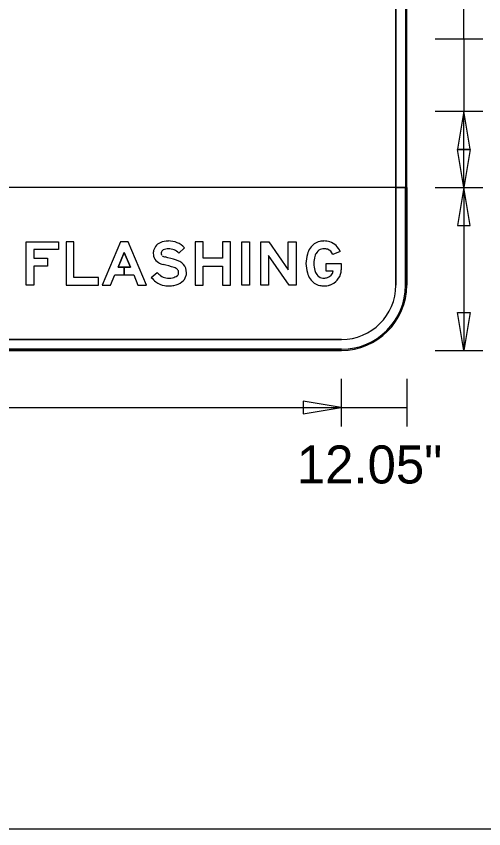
# Model space of a CAD drawing. Extents: x 17890628 to 17890817, y 17897493 to 17897992.
# Drawn here: x 17890789.24 to 17890796.4, y 17897520.54 to 17897533 of the extents above; entities that cross this region are included whole.
import ezdxf

# ---------------------------------------------------------------- set-up
doc = ezdxf.new("R2010")
doc.units = 0
for name, color, linetype in [('GSBWFill', 7, 'Continuous'), ('GSColorFill', 7, 'Continuous'), ('GSDims', 7, 'Continuous'), ('GSOutline', 7, 'Continuous'), ('SheetLinesMisc2_dp', 7, 'Continuous')]:
    doc.layers.add(name, color=color, linetype=linetype)

msp = doc.modelspace()

# ---------------------------------------------------------------- linework, layer by layer
at = {"layer": 'GSBWFill'}
for p, q in [((17890795.055, 17897536.876), (17890795.055, 17897528.876)), ((17890795.222, 17897528.876), (17890795.222, 17897536.876)), ((17890795.222, 17897530.376), (17890775.222, 17897530.376)), ((17890795.055, 17897530.21), (17890795.055, 17897530.376)), ((17890795.055, 17897530.376), (17890795.222, 17897530.376)), ((17890795.222, 17897530.376), (17890795.222, 17897528.876)), ((17890795.222, 17897528.876), (17890795.222, 17897530.376)), ((17890795.055, 17897528.876), (17890795.055, 17897530.21)), ((17890776.222, 17897528.043), (17890794.222, 17897528.043)), ((17890794.222, 17897528.043), (17890776.224, 17897528.043)), ((17890794.222, 17897527.876), (17890776.222, 17897527.876)), ((17890776.222, 17897527.876), (17890794.222, 17897527.876)), ((17890776.224, 17897527.876), (17890794.222, 17897527.876))]:
    msp.add_line(p, q, dxfattribs=at)
for points in [[(17890789.505, 17897529.17), (17890789.505, 17897528.876), (17890789.385, 17897528.876), (17890789.385, 17897529.543), (17890789.885, 17897529.543), (17890789.885, 17897529.423), (17890789.505, 17897529.423), (17890789.505, 17897529.29), (17890789.715, 17897529.29), (17890789.715, 17897529.17)], [(17890790.499, 17897528.876), (17890790.499, 17897528.993), (17890790.119, 17897528.993), (17890790.119, 17897529.543), (17890789.999, 17897529.543), (17890789.999, 17897528.876)], [(17890790.986, 17897529.153), (17890790.892, 17897529.153), (17890790.892, 17897529.033), (17890791.036, 17897529.033), (17890791.102, 17897528.876), (17890791.232, 17897528.876), (17890790.952, 17897529.543), (17890790.832, 17897529.543), (17890790.552, 17897528.876), (17890790.682, 17897528.876), (17890790.748, 17897529.033), (17890790.892, 17897529.033), (17890790.892, 17897529.153), (17890790.798, 17897529.153), (17890790.892, 17897529.376)], [(17890792.399, 17897529.29), (17890792.099, 17897529.29), (17890792.099, 17897529.543), (17890791.979, 17897529.543), (17890791.979, 17897528.876), (17890792.099, 17897528.876), (17890792.099, 17897529.17), (17890792.399, 17897529.17), (17890792.399, 17897528.876), (17890792.519, 17897528.876), (17890792.519, 17897529.543), (17890792.399, 17897529.543)], [(17890792.692, 17897528.876), (17890792.692, 17897529.543), (17890792.812, 17897529.543), (17890792.812, 17897528.876)], [(17890793.525, 17897529.543), (17890793.525, 17897528.876), (17890793.422, 17897528.876), (17890793.105, 17897529.333), (17890793.105, 17897528.876), (17890792.985, 17897528.876), (17890792.985, 17897529.543), (17890793.106, 17897529.543), (17890793.405, 17897529.111), (17890793.405, 17897529.543)]]:
    msp.add_lwpolyline(points, close=True, dxfattribs=at)
for points in [[(17890791.815, 17897529.451), (17890791.729, 17897529.367)], [(17890794.201, 17897529.392), (17890794.089, 17897529.347)], [(17890794.095, 17897529.09), (17890793.985, 17897529.09), (17890793.985, 17897529.21), (17890794.219, 17897529.21), (17890794.219, 17897529.114)], [(17890791.305, 17897528.994), (17890791.396, 17897529.073)]]:
    msp.add_lwpolyline(points, dxfattribs=at)
for centre, radius, start, end in [((17890791.511, 17897529.368), 0.174, 113.3248, 174.1421), ((17890791.568, 17897529.236), 0.318, 90, 113.3248), ((17890791.568, 17897529.21), 0.345, 44.4342, 90), ((17890793.943, 17897529.313), 0.24, 103.1315, 146.7742), ((17890793.954, 17897529.265), 0.289, 90, 103.1315), ((17890793.954, 17897529.275), 0.28, 71.2015, 90), ((17890793.961, 17897529.295), 0.259, 22.0367, 71.2015), ((17890791.511, 17897529.368), 0.0543, 113.3248, 174.1421), ((17890791.568, 17897529.236), 0.198, 90, 113.3248), ((17890791.568, 17897529.21), 0.225, 44.4342, 90), ((17890794.033, 17897529.254), 0.348, 146.7742, 163.4624), ((17890793.943, 17897529.313), 0.12, 103.1315, 146.7742), ((17890793.954, 17897529.265), 0.169, 90, 103.1315), ((17890793.954, 17897529.275), 0.16, 71.2015, 90), ((17890793.961, 17897529.295), 0.139, 22.0367, 71.2015), ((17890791.527, 17897529.367), 0.191, 174.1421, 201.2247), ((17890791.489, 17897529.352), 0.149, 201.2247, 240.1812), ((17890791.527, 17897529.367), 0.0706, 174.1421, 201.2247), ((17890791.489, 17897529.352), 0.029, 201.2247, 240.1812), ((17890791.558, 17897529.472), 0.168, 240.1812, 256.1067), ((17890790.74, 17897526.168), 3.236, 72.8961, 76.1067), ((17890794.183, 17897529.21), 0.505, 163.4624, 180), ((17890794.183, 17897529.21), 0.385, 163.4624, 180), ((17890794.033, 17897529.254), 0.228, 146.7742, 163.4624), ((17890791.558, 17897529.472), 0.288, 240.1812, 256.1067), ((17890790.74, 17897526.168), 3.116, 72.8961, 76.1067), ((17890791.598, 17897528.955), 0.32, 63.0108, 72.8961), ((17890791.662, 17897529.082), 0.178, 39.5561, 63.0108), ((17890791.646, 17897529.068), 0.199, 0, 39.5561), ((17890794.183, 17897529.21), 0.505, 180, 196.5376), ((17890794.183, 17897529.21), 0.385, 180, 196.5376), ((17890791.657, 17897529.298), 0.344, 220.8202, 232.6492), ((17890791.598, 17897528.955), 0.2, 63.0108, 72.8961), ((17890791.662, 17897529.082), 0.0579, 39.5561, 63.0108), ((17890791.679, 17897529.06), 0.045, 306.0677, 343.4972), ((17890791.646, 17897529.068), 0.0794, 0, 39.5561), ((17890791.651, 17897529.068), 0.0746, 343.4972, 0), ((17890791.651, 17897529.068), 0.195, 343.4972, 0), ((17890794.033, 17897529.165), 0.348, 196.5376, 213.2258), ((17890794.033, 17897529.165), 0.228, 196.5376, 213.2258), ((17890793.943, 17897529.106), 0.12, 213.2258, 256.8685), ((17890793.961, 17897529.124), 0.139, 288.7985, 345.418), ((17890793.961, 17897529.124), 0.259, 288.7985, 349.6765), ((17890794.021, 17897529.114), 0.198, 349.6765, 0), ((17890791.657, 17897529.298), 0.464, 220.8202, 232.6492), ((17890791.56, 17897529.171), 0.305, 232.6492, 260.7349), ((17890791.56, 17897529.171), 0.185, 232.6492, 260.7349), ((17890791.58, 17897529.295), 0.31, 260.7349, 270), ((17890791.58, 17897529.23), 0.245, 270, 281.6446), ((17890791.59, 17897529.182), 0.196, 281.6446, 306.0677), ((17890791.59, 17897529.182), 0.316, 281.6446, 306.0677), ((17890791.679, 17897529.06), 0.165, 306.0677, 343.4972), ((17890793.943, 17897529.106), 0.24, 213.2258, 256.8685), ((17890793.954, 17897529.154), 0.169, 256.8685, 270), ((17890793.954, 17897529.145), 0.16, 270, 288.7985), ((17890791.58, 17897529.295), 0.43, 260.7349, 270), ((17890791.58, 17897529.23), 0.365, 270, 281.6446), ((17890793.954, 17897529.154), 0.289, 256.8685, 270), ((17890793.954, 17897529.145), 0.28, 270, 288.7985), ((17890794.222, 17897528.876), 1, 270, 0), ((17890794.222, 17897528.876), 0.833, 270, 0), ((17890794.222, 17897528.876), 1, 270, 0), ((17890794.222, 17897528.876), 0.833, 270, 0), ((17890794.222, 17897528.876), 1, 270, 0)]:
    msp.add_arc(centre, radius, start, end, dxfattribs=at)
at = {"layer": 'GSColorFill'}
for p, q in [((17890795.055, 17897536.876), (17890795.055, 17897528.876)), ((17890795.205, 17897536.876), (17890795.205, 17897528.876)), ((17890795.222, 17897528.876), (17890795.222, 17897536.876)), ((17890795.222, 17897528.876), (17890795.222, 17897536.876)), ((17890795.222, 17897528.876), (17890795.222, 17897536.876)), ((17890795.222, 17897530.376), (17890775.222, 17897530.376)), ((17890795.055, 17897530.21), (17890795.055, 17897530.376)), ((17890795.055, 17897530.376), (17890795.222, 17897530.376)), ((17890795.205, 17897530.36), (17890795.205, 17897530.376)), ((17890795.205, 17897530.376), (17890795.222, 17897530.376)), ((17890795.205, 17897528.876), (17890795.205, 17897530.36)), ((17890795.222, 17897528.876), (17890795.222, 17897530.376)), ((17890795.222, 17897530.376), (17890795.222, 17897528.876)), ((17890795.222, 17897530.376), (17890795.222, 17897528.876)), ((17890795.055, 17897528.876), (17890795.055, 17897530.21)), ((17890776.222, 17897528.043), (17890794.222, 17897528.043)), ((17890794.222, 17897528.043), (17890776.224, 17897528.043)), ((17890794.222, 17897527.893), (17890776.222, 17897527.893)), ((17890776.222, 17897527.893), (17890794.222, 17897527.893)), ((17890776.222, 17897527.876), (17890794.222, 17897527.876)), ((17890776.222, 17897527.876), (17890794.222, 17897527.876)), ((17890776.222, 17897527.876), (17890794.222, 17897527.876)), ((17890794.222, 17897527.876), (17890776.222, 17897527.876)), ((17890794.222, 17897527.876), (17890776.222, 17897527.876)), ((17890776.224, 17897527.876), (17890794.222, 17897527.876))]:
    msp.add_line(p, q, dxfattribs=at)
for points in [[(17890789.505, 17897529.17), (17890789.505, 17897528.876), (17890789.385, 17897528.876), (17890789.385, 17897529.543), (17890789.885, 17897529.543), (17890789.885, 17897529.423), (17890789.505, 17897529.423), (17890789.505, 17897529.29), (17890789.715, 17897529.29), (17890789.715, 17897529.17)], [(17890790.499, 17897528.876), (17890790.499, 17897528.993), (17890790.119, 17897528.993), (17890790.119, 17897529.543), (17890789.999, 17897529.543), (17890789.999, 17897528.876)], [(17890790.986, 17897529.153), (17890790.892, 17897529.153), (17890790.892, 17897529.033), (17890791.036, 17897529.033), (17890791.102, 17897528.876), (17890791.232, 17897528.876), (17890790.952, 17897529.543), (17890790.832, 17897529.543), (17890790.552, 17897528.876), (17890790.682, 17897528.876), (17890790.748, 17897529.033), (17890790.892, 17897529.033), (17890790.892, 17897529.153), (17890790.798, 17897529.153), (17890790.892, 17897529.376)], [(17890792.399, 17897529.29), (17890792.099, 17897529.29), (17890792.099, 17897529.543), (17890791.979, 17897529.543), (17890791.979, 17897528.876), (17890792.099, 17897528.876), (17890792.099, 17897529.17), (17890792.399, 17897529.17), (17890792.399, 17897528.876), (17890792.519, 17897528.876), (17890792.519, 17897529.543), (17890792.399, 17897529.543)], [(17890792.692, 17897528.876), (17890792.692, 17897529.543), (17890792.812, 17897529.543), (17890792.812, 17897528.876)], [(17890793.525, 17897529.543), (17890793.525, 17897528.876), (17890793.422, 17897528.876), (17890793.105, 17897529.333), (17890793.105, 17897528.876), (17890792.985, 17897528.876), (17890792.985, 17897529.543), (17890793.106, 17897529.543), (17890793.405, 17897529.111), (17890793.405, 17897529.543)]]:
    msp.add_lwpolyline(points, close=True, dxfattribs=at)
for points in [[(17890791.815, 17897529.451), (17890791.729, 17897529.367)], [(17890794.201, 17897529.392), (17890794.089, 17897529.347)], [(17890794.095, 17897529.09), (17890793.985, 17897529.09), (17890793.985, 17897529.21), (17890794.219, 17897529.21), (17890794.219, 17897529.114)], [(17890791.305, 17897528.994), (17890791.396, 17897529.073)]]:
    msp.add_lwpolyline(points, dxfattribs=at)
for centre, radius, start, end in [((17890791.511, 17897529.368), 0.174, 113.3248, 174.1421), ((17890791.568, 17897529.236), 0.318, 90, 113.3248), ((17890791.568, 17897529.21), 0.345, 44.4342, 90), ((17890793.943, 17897529.313), 0.24, 103.1315, 146.7742), ((17890793.954, 17897529.265), 0.289, 90, 103.1315), ((17890793.954, 17897529.275), 0.28, 71.2015, 90), ((17890793.961, 17897529.295), 0.259, 22.0367, 71.2015), ((17890791.511, 17897529.368), 0.0543, 113.3248, 174.1421), ((17890791.568, 17897529.236), 0.198, 90, 113.3248), ((17890791.568, 17897529.21), 0.225, 44.4342, 90), ((17890794.033, 17897529.254), 0.348, 146.7742, 163.4624), ((17890793.943, 17897529.313), 0.12, 103.1315, 146.7742), ((17890793.954, 17897529.265), 0.169, 90, 103.1315), ((17890793.954, 17897529.275), 0.16, 71.2015, 90), ((17890793.961, 17897529.295), 0.139, 22.0367, 71.2015), ((17890791.527, 17897529.367), 0.191, 174.1421, 201.2247), ((17890791.489, 17897529.352), 0.149, 201.2247, 240.1812), ((17890791.527, 17897529.367), 0.0706, 174.1421, 201.2247), ((17890791.489, 17897529.352), 0.029, 201.2247, 240.1812), ((17890791.558, 17897529.472), 0.168, 240.1812, 256.1067), ((17890790.74, 17897526.168), 3.236, 72.8961, 76.1067), ((17890794.183, 17897529.21), 0.505, 163.4624, 180), ((17890794.183, 17897529.21), 0.385, 163.4624, 180), ((17890794.033, 17897529.254), 0.228, 146.7742, 163.4624), ((17890791.558, 17897529.472), 0.288, 240.1812, 256.1067), ((17890790.74, 17897526.168), 3.116, 72.8961, 76.1067), ((17890791.598, 17897528.955), 0.32, 63.0108, 72.8961), ((17890791.662, 17897529.082), 0.178, 39.5561, 63.0108), ((17890791.646, 17897529.068), 0.199, 0, 39.5561), ((17890794.183, 17897529.21), 0.505, 180, 196.5376), ((17890794.183, 17897529.21), 0.385, 180, 196.5376), ((17890791.657, 17897529.298), 0.344, 220.8202, 232.6492), ((17890791.598, 17897528.955), 0.2, 63.0108, 72.8961), ((17890791.662, 17897529.082), 0.0579, 39.5561, 63.0108), ((17890791.679, 17897529.06), 0.045, 306.0677, 343.4972), ((17890791.646, 17897529.068), 0.0794, 0, 39.5561), ((17890791.651, 17897529.068), 0.0746, 343.4972, 0), ((17890791.651, 17897529.068), 0.195, 343.4972, 0), ((17890794.033, 17897529.165), 0.348, 196.5376, 213.2258), ((17890794.033, 17897529.165), 0.228, 196.5376, 213.2258), ((17890793.943, 17897529.106), 0.12, 213.2258, 256.8685), ((17890793.961, 17897529.124), 0.139, 288.7985, 345.418), ((17890793.961, 17897529.124), 0.259, 288.7985, 349.6765), ((17890794.021, 17897529.114), 0.198, 349.6765, 0), ((17890791.657, 17897529.298), 0.464, 220.8202, 232.6492), ((17890791.56, 17897529.171), 0.305, 232.6492, 260.7349), ((17890791.56, 17897529.171), 0.185, 232.6492, 260.7349), ((17890791.58, 17897529.295), 0.31, 260.7349, 270), ((17890791.58, 17897529.23), 0.245, 270, 281.6446), ((17890791.59, 17897529.182), 0.196, 281.6446, 306.0677), ((17890791.59, 17897529.182), 0.316, 281.6446, 306.0677), ((17890791.679, 17897529.06), 0.165, 306.0677, 343.4972), ((17890793.943, 17897529.106), 0.24, 213.2258, 256.8685), ((17890793.954, 17897529.154), 0.169, 256.8685, 270), ((17890793.954, 17897529.145), 0.16, 270, 288.7985), ((17890791.58, 17897529.295), 0.43, 260.7349, 270), ((17890791.58, 17897529.23), 0.365, 270, 281.6446), ((17890793.954, 17897529.154), 0.289, 256.8685, 270), ((17890793.954, 17897529.145), 0.28, 270, 288.7985), ((17890794.222, 17897528.876), 1, 270, 0), ((17890794.222, 17897528.876), 1, 270, 0), ((17890794.222, 17897528.876), 0.833, 270, 0), ((17890794.222, 17897528.876), 1, 270, 0), ((17890794.222, 17897528.876), 0.983, 270, 0), ((17890794.222, 17897528.876), 1, 270, 0), ((17890794.222, 17897528.876), 1, 270, 0), ((17890794.222, 17897528.876), 0.833, 270, 0), ((17890794.222, 17897528.876), 1, 270, 0), ((17890794.222, 17897528.876), 0.983, 270, 0)]:
    msp.add_arc(centre, radius, start, end, dxfattribs=at)
at = {"layer": 'GSDims'}
for p, q in [((17890796.097, 17897532.655), (17890796.097, 17897533.489)), ((17890795.659, 17897532.655), (17890796.389, 17897532.655)), ((17890795.659, 17897532.655), (17890796.389, 17897532.655)), ((17890796.097, 17897532.655), (17890796.097, 17897531.547)), ((17890795.659, 17897531.547), (17890796.389, 17897531.547)), ((17890795.659, 17897531.547), (17890796.389, 17897531.547)), ((17890796.097, 17897530.376), (17890796.097, 17897531.547)), ((17890795.659, 17897530.376), (17890796.389, 17897530.376)), ((17890795.659, 17897530.376), (17890796.389, 17897530.376)), ((17890796.097, 17897530.376), (17890796.097, 17897527.876)), ((17890795.659, 17897527.876), (17890796.389, 17897527.876)), ((17890794.219, 17897527.439), (17890794.219, 17897526.71)), ((17890794.219, 17897527.439), (17890794.219, 17897526.71)), ((17890795.222, 17897527.439), (17890795.222, 17897526.71)), ((17890776.225, 17897527.001), (17890794.219, 17897527.001)), ((17890794.219, 17897527.001), (17890795.222, 17897527.001))]:
    msp.add_line(p, q, dxfattribs=at)
for points in [[(17890796.097, 17897531.547), (17890796, 17897530.964), (17890796.194, 17897530.964)], [(17890796.097, 17897530.376), (17890796, 17897530.96), (17890796.194, 17897530.96)], [(17890796.097, 17897530.376), (17890796, 17897529.793), (17890796.194, 17897529.793)], [(17890796.097, 17897527.876), (17890796, 17897528.46), (17890796.194, 17897528.46)], [(17890794.219, 17897527.001), (17890793.635, 17897527.098), (17890793.635, 17897526.904)]]:
    msp.add_lwpolyline(points, close=True, dxfattribs=at)
at = {"layer": 'GSOutline'}
for p, q in [((17890795.055, 17897528.876), (17890795.055, 17897536.876)), ((17890795.222, 17897528.876), (17890795.222, 17897536.876)), ((17890795.222, 17897530.376), (17890775.222, 17897530.376)), ((17890795.055, 17897530.21), (17890795.055, 17897530.376)), ((17890795.055, 17897530.376), (17890795.222, 17897530.376)), ((17890795.222, 17897530.376), (17890795.222, 17897528.876)), ((17890795.222, 17897528.876), (17890795.222, 17897530.376)), ((17890795.055, 17897528.876), (17890795.055, 17897530.21)), ((17890776.222, 17897528.043), (17890794.222, 17897528.043)), ((17890776.222, 17897528.043), (17890794.222, 17897528.043)), ((17890776.222, 17897527.876), (17890794.222, 17897527.876)), ((17890794.222, 17897527.876), (17890776.222, 17897527.876)), ((17890776.222, 17897527.876), (17890794.222, 17897527.876))]:
    msp.add_line(p, q, dxfattribs=at)
for points in [[(17890789.505, 17897529.17), (17890789.505, 17897528.876), (17890789.385, 17897528.876), (17890789.385, 17897529.543), (17890789.885, 17897529.543), (17890789.885, 17897529.423), (17890789.505, 17897529.423), (17890789.505, 17897529.29), (17890789.715, 17897529.29), (17890789.715, 17897529.17)], [(17890790.499, 17897528.876), (17890790.499, 17897528.993), (17890790.119, 17897528.993), (17890790.119, 17897529.543), (17890789.999, 17897529.543), (17890789.999, 17897528.876)], [(17890790.748, 17897529.033), (17890791.036, 17897529.033), (17890791.102, 17897528.876), (17890791.232, 17897528.876), (17890790.952, 17897529.543), (17890790.832, 17897529.543), (17890790.552, 17897528.876), (17890790.682, 17897528.876)], [(17890792.399, 17897529.29), (17890792.099, 17897529.29), (17890792.099, 17897529.543), (17890791.979, 17897529.543), (17890791.979, 17897528.876), (17890792.099, 17897528.876), (17890792.099, 17897529.17), (17890792.399, 17897529.17), (17890792.399, 17897528.876), (17890792.519, 17897528.876), (17890792.519, 17897529.543), (17890792.399, 17897529.543)], [(17890792.692, 17897528.876), (17890792.692, 17897529.543), (17890792.812, 17897529.543), (17890792.812, 17897528.876)], [(17890793.525, 17897529.543), (17890793.525, 17897528.876), (17890793.422, 17897528.876), (17890793.105, 17897529.333), (17890793.105, 17897528.876), (17890792.985, 17897528.876), (17890792.985, 17897529.543), (17890793.106, 17897529.543), (17890793.405, 17897529.111), (17890793.405, 17897529.543)], [(17890790.986, 17897529.153), (17890790.892, 17897529.376), (17890790.798, 17897529.153)]]:
    msp.add_lwpolyline(points, close=True, dxfattribs=at)
for points in [[(17890791.815, 17897529.451), (17890791.729, 17897529.367)], [(17890794.201, 17897529.392), (17890794.089, 17897529.347)], [(17890794.095, 17897529.09), (17890793.985, 17897529.09), (17890793.985, 17897529.21), (17890794.219, 17897529.21), (17890794.219, 17897529.114)], [(17890791.305, 17897528.994), (17890791.396, 17897529.073)]]:
    msp.add_lwpolyline(points, dxfattribs=at)
for centre, radius, start, end in [((17890791.511, 17897529.368), 0.174, 113.3248, 174.1421), ((17890791.568, 17897529.236), 0.318, 90, 113.3248), ((17890791.568, 17897529.21), 0.345, 44.4342, 90), ((17890793.943, 17897529.313), 0.24, 103.1315, 146.7742), ((17890793.954, 17897529.265), 0.289, 90, 103.1315), ((17890793.954, 17897529.275), 0.28, 71.2015, 90), ((17890793.961, 17897529.295), 0.259, 22.0367, 71.2015), ((17890791.511, 17897529.368), 0.0543, 113.3248, 174.1421), ((17890791.568, 17897529.236), 0.198, 90, 113.3248), ((17890791.568, 17897529.21), 0.225, 44.4342, 90), ((17890794.033, 17897529.254), 0.348, 146.7742, 163.4624), ((17890793.943, 17897529.313), 0.12, 103.1315, 146.7742), ((17890793.954, 17897529.265), 0.169, 90, 103.1315), ((17890793.954, 17897529.275), 0.16, 71.2015, 90), ((17890793.961, 17897529.295), 0.139, 22.0367, 71.2015), ((17890791.527, 17897529.367), 0.191, 174.1421, 201.2247), ((17890791.489, 17897529.352), 0.149, 201.2247, 240.1812), ((17890791.527, 17897529.367), 0.0706, 174.1421, 201.2247), ((17890791.489, 17897529.352), 0.029, 201.2247, 240.1812), ((17890791.558, 17897529.472), 0.168, 240.1812, 256.1067), ((17890790.74, 17897526.168), 3.236, 72.8961, 76.1067), ((17890794.183, 17897529.21), 0.505, 163.4624, 180), ((17890794.183, 17897529.21), 0.385, 163.4624, 180), ((17890794.033, 17897529.254), 0.228, 146.7742, 163.4624), ((17890791.558, 17897529.472), 0.288, 240.1812, 256.1067), ((17890790.74, 17897526.168), 3.116, 72.8961, 76.1067), ((17890791.598, 17897528.955), 0.32, 63.0108, 72.8961), ((17890791.662, 17897529.082), 0.178, 39.5561, 63.0108), ((17890791.646, 17897529.068), 0.199, 0, 39.5561), ((17890794.183, 17897529.21), 0.505, 180, 196.5376), ((17890794.183, 17897529.21), 0.385, 180, 196.5376), ((17890791.657, 17897529.298), 0.344, 220.8202, 232.6492), ((17890791.598, 17897528.955), 0.2, 63.0108, 72.8961), ((17890791.662, 17897529.082), 0.0579, 39.5561, 63.0108), ((17890791.679, 17897529.06), 0.045, 306.0677, 343.4972), ((17890791.646, 17897529.068), 0.0794, 0, 39.5561), ((17890791.651, 17897529.068), 0.0746, 343.4972, 0), ((17890791.651, 17897529.068), 0.195, 343.4972, 0), ((17890794.033, 17897529.165), 0.348, 196.5376, 213.2258), ((17890794.033, 17897529.165), 0.228, 196.5376, 213.2258), ((17890793.943, 17897529.106), 0.12, 213.2258, 256.8685), ((17890793.961, 17897529.124), 0.139, 288.7985, 345.418), ((17890793.961, 17897529.124), 0.259, 288.7985, 349.6765), ((17890794.021, 17897529.114), 0.198, 349.6765, 0), ((17890791.657, 17897529.298), 0.464, 220.8202, 232.6492), ((17890791.56, 17897529.171), 0.305, 232.6492, 260.7349), ((17890791.56, 17897529.171), 0.185, 232.6492, 260.7349), ((17890791.58, 17897529.295), 0.31, 260.7349, 270), ((17890791.58, 17897529.23), 0.245, 270, 281.6446), ((17890791.59, 17897529.182), 0.196, 281.6446, 306.0677), ((17890791.59, 17897529.182), 0.316, 281.6446, 306.0677), ((17890791.679, 17897529.06), 0.165, 306.0677, 343.4972), ((17890793.943, 17897529.106), 0.24, 213.2258, 256.8685), ((17890793.954, 17897529.154), 0.169, 256.8685, 270), ((17890793.954, 17897529.145), 0.16, 270, 288.7985), ((17890791.58, 17897529.295), 0.43, 260.7349, 270), ((17890791.58, 17897529.23), 0.365, 270, 281.6446), ((17890793.954, 17897529.154), 0.289, 256.8685, 270), ((17890793.954, 17897529.145), 0.28, 270, 288.7985), ((17890794.222, 17897528.876), 1, 270, 0), ((17890794.222, 17897528.876), 0.833, 270, 0), ((17890794.222, 17897528.876), 1, 270, 0), ((17890794.222, 17897528.876), 0.833, 270, 0), ((17890794.222, 17897528.876), 1, 270, 0)]:
    msp.add_arc(centre, radius, start, end, dxfattribs=at)
at = {"layer": 'SheetLinesMisc2_dp'}
msp.add_line((17890759.649, 17897520.539), (17890810.82, 17897520.539), dxfattribs=at)

# ---------------------------------------------------------------- texts
at = {"layer": 'GSDims'}
msp.add_text('12.05"', height=0.5833, dxfattribs=at).set_placement((17890793.538, 17897525.835))

doc.saveas('drawing.dxf')
